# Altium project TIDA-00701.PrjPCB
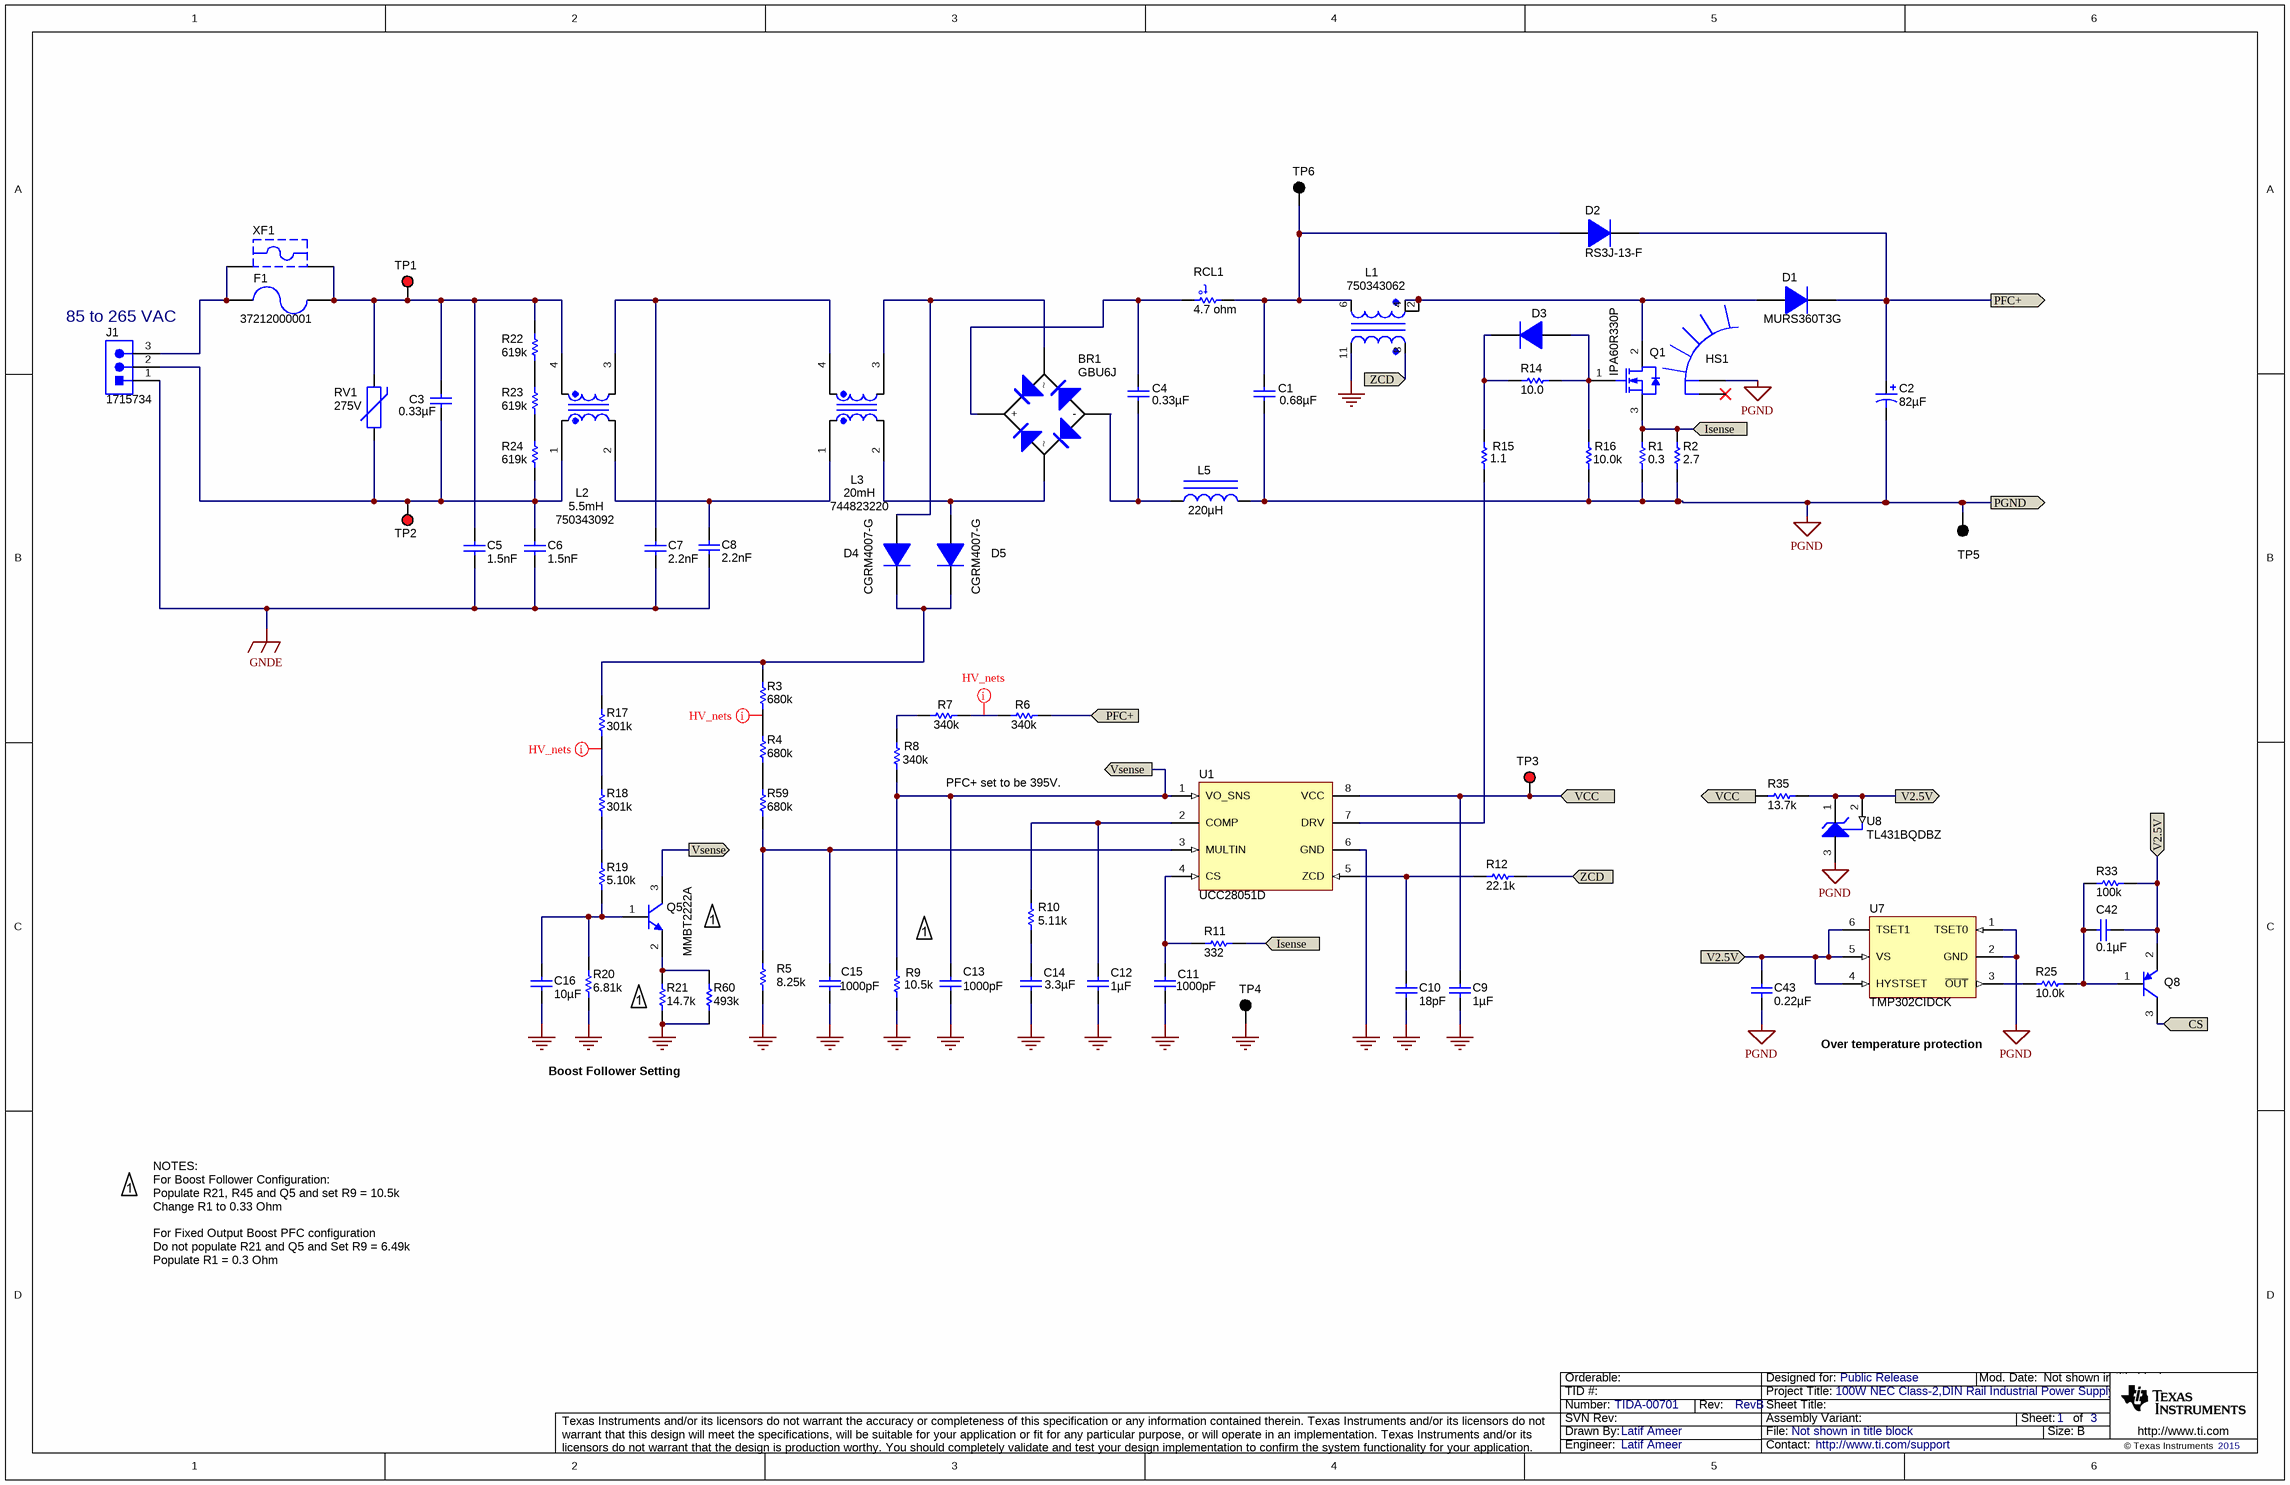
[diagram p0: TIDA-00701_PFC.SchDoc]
CopyrightYear: 2015; PCB_Layout: Manjunatha T N; PCB_Rev: RevB; PRJ_Customer: Public Release; PRJ_Engineer: Latif Ameer; PRJ_Number: TIDA-00701; PRJ_Title: 100W NEC Class-2,DIN Rail Industrial Power Supply; SCH_Rev: RevB; TechSupport: http://www.ti.com/support
3 sheets, 178 parts. Net scope: flat (ports and power ports of the same name join across sheets).
Board file: TIDA-00701_RevB.PcbDoc
Sheets:
  TIDA-00701_PFC.SchDoc
  TIDA-00701_Flyback.SchDoc
  Hardware_ANSI-B.SchDoc

## Sheet TIDA-00701_PFC.SchDoc
size 431 x 279 mm; Date: Not shown in title block; ApprovedBy: Not shown in title block; CheckedBy: Not shown in title block; Author: Not shown in title block; CompanyName: Not shown in title block; DrawnBy: Latif Ameer; Engineer: Not shown in title block; Organization: Not shown in title block; Address1: Not shown in title block; Address2: Not shown in title block; Address3: Not shown in title block; Address4: Not shown in title block; DocumentNumber: 1; Revision: Use project parameter SCH_Rev; SheetNumber: 1; SheetTotal: 3; PageSetup: Record=PageOptions¦CenterHorizontal=True¦CenterVertical=True¦PrintScale=1.00¦XCorrection=1.00¦YCorrection=1.00¦PrintKind=0¦BorderSize=5000000¦LeftOffset=0¦BottomOffset=0¦Orientation=2¦PaperLength=1000¦PaperWidth=1000¦Scale=100¦PaperSource=15¦PrintQuality=600¦MediaType=1¦DitherType=10¦PaperKind=Letter¦PrintScaleMode=1

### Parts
BR1  GBU6J  [GBU]
C1  ValueDisplayed: 0.68µF  [B32922_18.5mm]  (hidden comment: B32922C3684M)
C2  ValueDisplayed: 82µF  [CAPPRD750W80D1800H3150]  (hidden comment: UCY2W820MHD6)
C3  ValueDisplayed: 0.33µF  [B32922_14.5mm]  (hidden comment: B32922C3334M)
C4  ValueDisplayed: 0.33µF  [B32922_14.5mm]  (hidden comment: B32922C3334M)
C5  ValueDisplayed: 1.5nF  [E_900x700x900]  (hidden comment: CS75ZU2GA152MYNKA)
C6  ValueDisplayed: 1.5nF  [E_900x700x900]  (hidden comment: CS75ZU2GA152MYNKA)
C7  ValueDisplayed: 2.2nF  [E_900x700x900]  (hidden comment: CS80ZU2GA222MYNKA)
C8  ValueDisplayed: 2.2nF  [E_900x700x900]  (hidden comment: CS80ZU2GA222MYNKA)
C9  ValueDisplayed: 1µF  [0603]  (hidden comment: GRM188R61H105KAALD)
C10  ValueDisplayed: 18pF  [0603]  (hidden comment: GRM1885C1H180JA01D)
C11  ValueDisplayed: 1000pF  [0603]  (hidden comment: C1608C0G1H102J)
C12  ValueDisplayed: 1µF  [0603]  (hidden comment: C1608X5R1C105K)
C13  ValueDisplayed: 1000pF  [0603]  (hidden comment: C1608C0G1H102J)
C14  ValueDisplayed: 3.3µF  [0603]  (hidden comment: C1608X5R1E335K080AC)
C15  ValueDisplayed: 1000pF  [0603]  (hidden comment: C1608C0G1H102J)
C16  ValueDisplayed: 10µF  [0805_HV]  (hidden comment: C2012X5R1E106K125AB)
C42  ValueDisplayed: 0.1µF  [0603]  (hidden comment: GRM188R61C104KA01D)
C43  ValueDisplayed: 0.22µF  [0603]  (hidden comment: C1608X7R1C224K)
D1  MURS360T3G  [SMC]
D2  RS3J-13-F  [SMC]
D3  MMDL914-TP  [sod-323]  (value not drawn)
D4  CGRM4007-G  [MINI-SMA]
D5  CGRM4007-G  [MINI-SMA]
F1  37212000001  [FUSE_372]
HS1  593002B03400G  [HEATSINK_593002B03400G]  (value not drawn)
J1  1715734  [Phoenix_1715734]
L1  750343062  [XFMR_CTX16-17298]
L2  750343092  ValueDisplayed: 5.5mH  [750311982]
L3  744823220  ValueDisplayed: 20mH  [IND_WE-CMB_M]
L5  ValueDisplayed: 220µH  [IND_2118-V-RC]  (hidden comment: 2116-V-RC)
Q1  IPA60R330P  [TO-220AB]
Q5  MMBT2222A  [SOT-23]
Q8  MMBT4403WT1G  [SOT-323]  (value not drawn)
R1  ValueDisplayed: 0.3  [2010]  (hidden comment: CSRN2010FKR300)
R2  ValueDisplayed: 2.7  [2010]  (hidden comment: CRCW20102R70JNEF)
R3  ValueDisplayed: 680k  [1206]  (hidden comment: RC1206FR-07680KL)
R4  ValueDisplayed: 680k  [1206]  (hidden comment: RC1206FR-07680KL)
R5  ValueDisplayed: 8.25k  [0805_HV]  (hidden comment: CRCW08058K25FKEA)
R6  ValueDisplayed: 340k  [1206]  (hidden comment: CRCW1206340KFKEA)
R7  ValueDisplayed: 340k  [1206]  (hidden comment: CRCW1206340KFKEA)
R8  ValueDisplayed: 340k  [1206]  (hidden comment: CRCW1206340KFKEA)
R9  ValueDisplayed: 10.5k  [0603]  (hidden comment: CRCW060310K5FKEA)
R10  ValueDisplayed: 5.11k  [0603]  (hidden comment: CRCW06035K11FKEA)
R11  ValueDisplayed: 332  [0603]  (hidden comment: CRCW0603332RFKEA)
R12  ValueDisplayed: 22.1k  [0603]  (hidden comment: CRCW060322K1FKEA)
R14  ValueDisplayed: 10.0  [0805_HV]  (hidden comment: CRCW080510R0FKEA)
R15  ValueDisplayed: 1.1  [0805_HV]  (hidden comment: CRCW08051R10JNEA)
R16  ValueDisplayed: 10.0k  [0603]  (hidden comment: CRCW060310K0FKEA)
R17  ValueDisplayed: 301k  [1206]  (hidden comment: CRCW1206301KFKEA)
R18  ValueDisplayed: 301k  [1206]  (hidden comment: CRCW1206301KFKEA)
R19  ValueDisplayed: 5.10k  [1206]  (hidden comment: RC1206FR-075K1L)
R20  ValueDisplayed: 6.81k  [0805_HV]  (hidden comment: CRCW08056K81FKEA)
R21  ValueDisplayed: 14.7k  [0603]  (hidden comment: RC0603FR-0714K7L)
R22  ValueDisplayed: 619k  [1206]  (hidden comment: CRCW1206619KFKEA)
R23  ValueDisplayed: 619k  [1206]  (hidden comment: CRCW1206619KFKEA)
R24  ValueDisplayed: 619k  [1206]  (hidden comment: CRCW1206619KFKEA)
R25  ValueDisplayed: 10.0k  [0603]  (hidden comment: CRCW060310K0FKEA)
R33  ValueDisplayed: 100k  [0603]  (hidden comment: CRCW0603100KFKEA)
R35  ValueDisplayed: 13.7k  [0603]  (hidden comment: CRCW060313K7FKEA)
R59  ValueDisplayed: 680k  [1206]  (hidden comment: RC1206FR-07680KL)
R60  ValueDisplayed: 493k  [0603]  (hidden comment: RT0603BRD07493KL)
RCL1  value 4.7 ohm  [THERM_B57236S0]  (hidden comment: B57236S479M)
RV1  value 275V  [VAR_S10K275E2]  (hidden comment: S10K275E2)
TP1  5000  [Keystone5000]  (value not drawn)
TP2  5000  [Keystone5000]  (value not drawn)
TP3  5000  [Keystone5000]  (value not drawn)
TP4  5001  [Keystone5001]  (value not drawn)
TP5  5001  [Keystone5001]  (value not drawn)
TP6  5001  [Keystone5001]  (value not drawn)
U1  UCC28051D  [D0008A_N]
U7  TMP302CIDCK  [DCK0006A_N]
U8  TL431BQDBZ  [DBZ0003A_L]
XF1  56000001009  [FuseHolder_560000010]  (value not drawn)

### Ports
CS (in), Isense (in), PFC+ (in), PFC+ (out), PGND (out), V2.5V (in), V2.5V (out), VCC (in), Vsense (out), ZCD, ZCD (in)

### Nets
GND: C1.2 C2.2(-) C9.2 C10.2 C11.2 C12.2 C13.2 C14.2 C15.2 C16.2 C43.2 HS1.1 L1.11 L5.2 R1.1 R2.1 R5.1 R9.1 R16.2 R20.2 R21.2 R60.1 TP4.1 TP5.1 U1.6(GND) U7.1(TSET0) U7.2(GND) U8.3(ANODE) ; port PGND  [also labelled PGND]
GNDE: C5.2 C6.2 C7.2 C8.2 J1.1
VCC: C9.1 R35.1 TP3.1 U1.8(VCC) ; port VCC
NetBR1_1: BR1.1(+) C4.1 RCL1.2
NetBR1_2: BR1.2 D4.2(A) L3.3
NetBR1_3: BR1.3 D5.2(A) L3.2
NetBR1_4: BR1.4(-) C4.2 L5.1
NetC1_1: C1.1 D2.2(A) L1.6 RCL1.1 TP6.1
NetC2_1: C2.1(+) D1.1(K) D2.1(K) R6.1 ; port PFC+
NetC3_1: C3.1 C5.1 F1.1 L2.4 R22.1 RV1.2 TP1.1 XF1.1
NetC3_2: C3.2 C6.1 J1.2 L2.1 R24.2 RV1.1 TP2.1
NetC7_1: C7.1 L2.3 L3.4
NetC8_1: C8.1 L2.2 L3.1
NetC10_1: C10.1 R12.1 U1.5(ZCD)
NetC11_1: C11.1 R11.1 U1.4(CS)
NetC12_1: C12.1 R10.2 U1.2(COMP)
NetC13_1: C13.1 Q5.3(C) R8.1 R9.2 U1.1(VO_SNS) ; port Vsense
NetC14_1: C14.1 R10.1
NetC15_1: C15.1 R5.2 R59.2 U1.3(MULTIN)
NetC16_1: C16.1 Q5.1(B) R19.1 R20.1
NetC36_1: Q8.3(C) ; port CS
NetC42_1: C42.1 Q8.1(B) R25.2 R33.1
NetC42_2: C42.2 C43.1 Q8.2(E) R33.2 R35.2 U7.4(HYSTSET) U7.5(VS) U7.6(TSET1) U8.1(CATHODE) U8.2(REF) ; port V2.5V
NetD1_2: D1.2(A) L1.2 L1.4 Q1.2(D)
NetD3_1: D3.1(K) R14.1 R15.2
NetD3_2: D3.2(A) Q1.1(G) R14.2 R16.1
NetD4_1: D4.1(K) D5.1(K) R3.1 R17.2
NetF1_2: F1.2 J1.3 XF1.2
NetL1_8: L1.8 R12.2 ; port ZCD
NetQ1_3: Q1.3(S) R1.2 R2.2 R11.2 ; port Isense
NetQ5_2: Q5.2(E) R21.1 R60.2
NetR3_2: R3.2 R4.1
NetR4_2: R4.2 R59.1
NetR6_2: R6.2 R7.2
NetR7_1: R7.1 R8.2
NetR15_1: R15.1 U1.7(DRV)
NetR17_1: R17.1 R18.1
NetR18_2: R18.2 R19.2
NetR22_2: R22.2 R23.1
NetR23_2: R23.2 R24.1
NetR25_1: R25.1 U7.3(~{OUT})

Not connected (* = marked no-connect by the designer): HS1 2*

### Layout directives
net class HV_net: (no net found under the mark), NetR6_2, NetR17_1

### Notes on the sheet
- (near J1) 85 to 265 VAC
- PFC+ set to be 395V.
- Boost Follower Setting
- Over temperature protection
- NOTES:
  For Boost Follower Configuration:
  Populate R21, R45 and Q5 and set R9 = 10.5k
  Change R1 to 0.33 Ohm
  For Fixed Output Boost PFC configuration
  Do not populate R21 and Q5 and Set R9 = 6.49k
  Populate R1 = 0.3 Ohm

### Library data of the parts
BR1 = GBU4A-BP: RECT BRIDGE GPP 6A 600V GBU; Manufacturer: Micro Commercial Components; CompType: Diode; U/M: EA; Vf_V: 0.95; Io_A: 4; Vr_V: 50; Value2: 50V; TJmax_C: 150; RJC_CperW: 2.2
C1 = B32922C3684M: CAP, Film, 0.68 µF, 630 V, +/- 20%, TH; Manufacturer: TDK; Polarized: N; CompType: Capacitor; Value: 0.68uF; U/M: EA; Cap_F: 0.00000068; Tolerance_%: 20; Value1: Unknown; VDC_V: 630; Value2: 630V; TaMax_C: 110
C2 = EEUED2E820S: CAP ALUM 82UF 20% 450V RADIAL; Manufacturer: Nichicon; Polarized: Y; CompType: Capacitor; U/M: EA; Cap_F: 0.000082; Tolerance_%: 20; VDC_V: 450; IRMS_A: 730mA; TaMin_C: -25; TaMax_C: 105; AC_Derating: 0.3
C3 C4 = B32922C3334M: CAP, Film, 0.33 µF, 630 V, +/- 20%, TH; Manufacturer: TDK; Polarized: N; CompType: Capacitor; Value: 0.33uF; U/M: EA; Cap_F: 0.00000033; Tolerance_%: 20; Value1: Unknown; VDC_V: 630; Value2: 630V; TaMax_C: 110; AEC Category: Q200
C5 C6 = DE6E3KJ222MN3A: CAP CER 1500PF 300VAC 20% RADIAL; Manufacturer: TDK Corporation; Polarized: N; CompType: Capacitor; Value: 1.5nF; U/M: EA; Cap_F: 0.0000000022; Tolerance_%: 20; Value1: Unknown; VDC_V: 300; Value2: 300V; TempCo: E; TaMin_C: -40; TaMax_C: 125
C7 C8 = DE6E3KJ222MN3A: CAP CER 2200PF 300VAC 20% RADIAL; Manufacturer: TDK Corporation; Polarized: N; CompType: Capacitor; Value: 2.2nF; U/M: EA; Cap_F: 0.0000000022; Tolerance_%: 20; Value1: Unknown; VDC_V: 300; Value2: 300V; TempCo: E; TaMin_C: -40; TaMax_C: 125
C9 = GRM188R61H105KAALD: CAP, CERM, 1 µF, 50 V, +/- 10%, X5R, 0603; Manufacturer: MuRata; Polarized: N; CompType: Capacitor; Value: 1uF; U/M: EA; Cap_F: 0.000001; Tolerance_%: 10; Value1: Unknown; VDC_V: 50; Value2: 50V; TaMin_C: -55; TaMax_C: 85
C10 = GRM1885C1H180JA01D: CAP, CERM, 18 pF, 50 V, +/- 5%, C0G/NP0, 0603; Manufacturer: MuRata; Polarized: N; CompType: Capacitor; Value: 18pF; U/M: EA; Cap_F: 0.000000000018; Tolerance_%: 5; Value1: Unknown; VDC_V: 50; Value2: 50V; TaMin_C: -55; TaMax_C: 125
C11 C13 C15 = C1608C0G1H102J: CAP, CERM, 1000 pF, 50 V, +/- 5%, C0G/NP0, 0603; Manufacturer: TDK; Polarized: N; CompType: Capacitor; Value: 1000pF; U/M: EA; Cap_F: 0.000000001; Tolerance_%: 5; ESR_ohm: 0.0563; Value1: 0.0563 ohm; VDC_V: 50; Value2: 50V; TaMin_C: -55; TaMax_C: 125
C12 = C1608X5R1C105K: CAP, CERM, 1 µF, 16 V, +/- 10%, X5R, 0603; Manufacturer: TDK; Polarized: N; CompType: Capacitor; Value: 1uF; U/M: EA; Cap_F: 0.000001; Tolerance_%: 10; ESR_ohm: 0.0057; Value1: 0.0057 ohm; VDC_V: 16; Value2: 16V; TaMin_C: -55; TaMax_C: 85; AEC Category: Q200
C14 = C1608X5R1E335K080AC: CAP, CERM, 3.3 µF, 25 V, +/- 10%, X5R, 0603; Manufacturer: TDK; Polarized: N; CompType: Capacitor; Value: 3.3uF; U/M: EA; Cap_F: 0.0000033; Tolerance_%: 10; Value1: Unknown; VDC_V: 25; Value2: 25V; TaMin_C: -55; TaMax_C: 85
C16 = C2012X5R1E106K125AB: CAP, CERM, 10 µF, 25 V, +/- 10%, X5R, 0805; Manufacturer: TDK; Polarized: N; CompType: Capacitor; Value: 10uF; U/M: EA; Cap_F: 0.00001; Tolerance_%: 10; Value1: Unknown; VDC_V: 25; Value2: 25V; TaMin_C: -55; TaMax_C: 85; Cap_Case: 0805
C42 = GRM188R61C104KA01D: CAP, CERM, 0.1 µF, 16 V, +/- 10%, X5R, 0603; Manufacturer: MuRata; Polarized: N; CompType: Capacitor; Value: 0.1uF; U/M: EA; Cap_F: 0.0000001; Tolerance_%: 10; Value1: Unknown; VDC_V: 16; Value2: 16V; TaMin_C: -55; TaMax_C: 85
C43 = C1608X7R1C224K: CAP, CERM, 0.22 µF, 16 V, +/- 10%, X7R, 0603; Manufacturer: TDK; Polarized: N; CompType: Capacitor; Value: 0.22uF; U/M: EA; Cap_F: 0.00000022; Tolerance_%: 10; ESR_ohm: 0.0125; Value1: 0.0125 ohm; VDC_V: 16; Value2: 16V; TaMin_C: -55; TaMax_C: 125
D1 = MURS360T3G: Diode, Ultrafast, 600 V, 3 A, SMC; Manufacturer: ON Semiconductor; U/M: EA; Vf_V: 1.25; Value: 600V; Value1: 3A; Value2: 1.25V; Io_A: 3; Vr_V: 600; TJmax_C: 175; RJC_CperW: 11
D2 = RS3K-E3/9AT: DIODE GEN PURP 600V 3A SMC; Manufacturer: Diodes Incorporated; U/M: EA; Vf_V: 1.3; Value2: 1.3V; Io_A: 3; Vr_V: 600; TJmax_C: 150; RJC_CperW: 50; Type: Switching
D3 = MMDL914-TP: Diode, Switching, 100 V, 0.2 A, SOD-323; Manufacturer: Micro Commercial Components; Value: 100V; U/M: EA; Vf_V: 1; Value1: 0.2A; Value2: 1V; Io_A: 0.2; Vr_V: 100; TJmax_C: 150; RJC_CperW: 635
D4 D5 = CGRM4007-G: Diode, P-N, 1000 V, 1 A, 3.9x1.7x1.8mm; Manufacturer: Comchip Technology; U/M: EA; Vf_V: 1.1; Value: 1000V; Value1: 1A; Value2: 1.1V; Io_A: 1; Vr_V: 1000; TJmax_C: 150
F1 = 37212000001: Fuse, 2 A, 250 V, TH; Manufacturer: Littelfuse; U/M: EA; OpeningTime_200%_max: 2; VDC_V: 250; Vdrop: 0.085; Soldering_Wave_MaxTemp_C: 260; Soldering_Wave_MaxTime_s: 5
HS1 = 593002B00000G: HEATSINK TWISTED FIN TO-220 Vertical; Manufacturer: Aavid Thermalloy; SymbolCreator: a0799628; Value: 13.4°C/W
J1 = 1715734: TERM BLOCK 3POS 5.08MM, TH; Manufacturer: Phoenix Contact; SymbolCreator: a0799628; CompType: Header; U/M: EA
L1 = XFMR_CTX16-17298: PFC choke with primary side sensing winding; Manufacturer: Wurth; Value: 330uH
L2 = 744823210: Coupled inductor, 5.5mH+/-32%, 2.5 A, 0.040 ohm; Manufacturer: Wurth Elektronik; Value: 5.5mH=/-32%; Ind_H: 5.5e-3; Tolerance_%: 32
L3 = 744823210: Coupled inductor, 20 mH, 1.5A, 0.270 ohm, +/- 30%, TH; Manufacturer: Wurth Elektronik; SymbolCreator: a0412235; Value: 20mH; Ind_H: 20.0E-3; DCR_ohm: 0.270; Tolerance_%: 30
L5 = PM2110-1R0M-RC: Inductor, Toroid, 220µH, 2.4 A, 0.120 ohm, TH; Manufacturer: Bourns; Value: 220uH; Ind_H: 220E-6; Imax_A: 2.4; Irms: 2.4A @ 30C rise; DCR_ohm: 0.120; Value2: 2.4A; AEC Category: Q200
Q1 = IPP60R190P6: MOSFET N-CH 600V 10.6A TO220; PartNumber: IPA60R330P6XKSA1; Manufacturer: Infineon Technologies; SymbolCreator: x0199378
Q5 = MMBT2222A, Fairchild Semiconductor: Transistor, NPN, 40 V, 0.15 A, SOT-23; CompType: BJT; PNP: 0; NPN: 1; Vceo_V: 40; Vcesat1_V: 0.3; Value: 40 V; IcRated_A: 0.15; Value1: 0.15 A; HfeMax: 300; TaMin_C: -55; TaMax_C: 150; U/M: EA; AEC Category: Q101
Q8 = MMBT2907A, Fairchild Semiconductor: Transistor, PNP, 40 V, 0.6 A, SOT-323; CompType: BJT; PNP: 1; NPN: 0; Vceo_V: 40; Vcesat1_V: 0.75; Value: 40 V; IcRated_A: 0.8; Value1: 0.6 A; HfeMax: 300; TaMin_C: -55; TaMax_C: 150; U/M: EA
R1 = CSRN2010FKR300: RES, 0.3, 1%, 1 W, 2010; Manufacturer: Stackpole Electronics Inc; CompType: Resistor; Value: 0.3; Value_Code: R300; Tolerance_%: 1; Value2: 1W; TempCo: 250 ppm/C; EIA_Code: E96; U/M: EA; AEC Category: Q200
R2 = CRCW20102R70JNEF: RES, 2.7, 5%, 0.75 W, 2010; Manufacturer: Vishay-Dale; CompType: Resistor; Value: 2.7; Value_Code: 2R70; Tolerance_%: 5; Power_W: 0.75; Value2: 0.75W; VDC_V: 400; TempCo: 200 ppm/C; EIA_Code: E24; U/M: EA
R3 R4 R59 = RC1206FR-07680KL: RES, 680 k, 1%, 0.25 W, 1206; Manufacturer: Yageo America; Value: 680k; CompType: Resistor; Res_ohm: 680000; Tolerance_%: 1; Power_W: 0.25; Value2: 0.25W; VDC_V: 200; TempCo: 100 ppm/C; U/M: EA
R5 = CRCW08058K25FKEA: RES, 8.25 k, 1%, 0.125 W, 0805; Manufacturer: Vishay-Dale; CompType: Resistor; Value: 8.25k; Res_ohm: 8250; Value_Code: 8k25; Tolerance_%: 1; Power_W: 0.125; Value2: 0.125W; VDC_V: 150; TempCo: 100 ppm/C; EIA_Code: E96; U/M: EA; AEC Category: Q200
R6-R8 = CRCW1206340KFKEA: RES, 340 k, 1%, 0.25 W, 1206; Manufacturer: Vishay-Dale; Value: 340k; CompType: Resistor; Res_ohm: 340000; Tolerance_%: 1; Power_W: 0.25; Value2: 0.25W; VDC_V: 200; TempCo: 100 ppm/C; EIA_Code: E96; U/M: EA
R9 = CRCW060310K5FKEA: RES, 10.5 k, 1%, 0.1 W, 0603; Manufacturer: Vishay-Dale; CompType: Resistor; Value: 10.5k; Res_ohm: 10500; Value_Code: 10k5; Tolerance_%: 1; Power_W: 0.1; Value2: 0.1W; VDC_V: 75; TempCo: 100 ppm/C; EIA_Code: E96; U/M: EA; AEC Category: Q200
R10 = CRCW06035K11FKEA: RES, 5.11 k, 1%, 0.1 W, 0603; Manufacturer: Vishay-Dale; CompType: Resistor; Value: 5.11k; Res_ohm: 5110; Value_Code: 5k11; Tolerance_%: 1; Power_W: 0.1; Value2: 0.1W; VDC_V: 75; TempCo: 100 ppm/C; EIA_Code: E96; U/M: EA
R11 = CRCW0603332RFKEA: RES, 332, 1%, 0.1 W, 0603; Manufacturer: Vishay-Dale; CompType: Resistor; Value: 332; Value_Code: 332R; Tolerance_%: 1; Power_W: 0.1; Value2: 0.1W; VDC_V: 75; TempCo: 100 ppm/C; EIA_Code: E96; U/M: EA
R12 = CRCW060322K1FKEA: RES, 22.1 k, 1%, 0.1 W, 0603; Manufacturer: Vishay-Dale; CompType: Resistor; Value: 22.1k; Res_ohm: 22100; Value_Code: 22k1; Tolerance_%: 1; Power_W: 0.1; Value2: 0.1W; VDC_V: 75; TempCo: 100 ppm/C; EIA_Code: E96; U/M: EA
R14 = CRCW080510R0FKEA: RES, 10.0, 1%, 0.125 W, 0805; Manufacturer: Vishay-Dale; CompType: Resistor; Value: 10.0; Res_ohm: 10; Value_Code: 10R0; Tolerance_%: 1; Power_W: 0.125; Value2: 0.125W; VDC_V: 150; TempCo: 100 ppm/C; EIA_Code: E96; U/M: EA
R15 = CRCW08051R10JNEA: RES, 1.1, 5%, 0.125 W, 0805; Manufacturer: Vishay-Dale; CompType: Resistor; Value: 1.1; Value_Code: 1R10; Tolerance_%: 5; Power_W: 0.125; Value2: 0.125W; VDC_V: 150; TempCo: 200 ppm/C; EIA_Code: E24; U/M: EA; AEC Category: Q200
R16 R25 = CRCW060310K0FKEA: RES, 10.0 k, 1%, 0.1 W, 0603; Manufacturer: Vishay-Dale; CompType: Resistor; Value: 10.0k; Res_ohm: 10000; Value_Code: 10k0; Tolerance_%: 1; Power_W: 0.1; Value2: 0.1W; VDC_V: 75; TempCo: 100 ppm/C; EIA_Code: E96; U/M: EA
R17 R18 = CRCW1206301KFKEA: RES, 301 k, 1%, 0.25 W, 1206; Manufacturer: Vishay-Dale; CompType: Resistor; Value: 301k; Res_ohm: 301000; Tolerance_%: 1; Power_W: 0.25; Value2: 0.25W; VDC_V: 200; TempCo: 100 ppm/C; EIA_Code: E96; U/M: EA; AEC Category: Q200
R19 = RC1206FR-075K1L: RES, 5.10 k, 1%, 0.25 W, 1206; Manufacturer: Yageo America; CompType: Resistor; Value: 5.10k; Res_ohm: 5100; Value_Code: 5k10; Tolerance_%: 1; Power_W: 0.25; Value2: 0.25W; VDC_V: 200; TempCo: 100 ppm/C; U/M: EA; AEC Category: Q200
R20 = CRCW08056K81FKEA: RES, 6.81 k, 1%, 0.125 W, 0805; Manufacturer: Vishay-Dale; CompType: Resistor; Value: 6.81k; Res_ohm: 6810; Value_Code: 6k81; Tolerance_%: 1; Power_W: 0.125; Value2: 0.125W; VDC_V: 150; TempCo: 100 ppm/C; EIA_Code: E96; U/M: EA; AEC Category: Q200
R21 = RC0603FR-0714K7L: RES, 14.7 k, 1%, 0.1 W, 0603; Manufacturer: Yageo America; CompType: Resistor; Value: 14.7k; Res_ohm: 14700; Value_Code: 14k7; Tolerance_%: 1; Power_W: 0.1; Value2: 0.1W; VDC_V: 150; TempCo: 200 ppm/C; EIA_Code: E96; U/M: EA; AEC Category: Q200
R22-R24 = CRCW1206619KFKEA: RES, 619 k, 1%, 0.25 W, 1206; Manufacturer: Vishay-Dale; Value: 619k; CompType: Resistor; Res_ohm: 619000; Tolerance_%: 1; Power_W: 0.25; Value2: 0.25W; VDC_V: 200; TempCo: 100 ppm/C; EIA_Code: E96; U/M: EA; AEC Category: Q200
R33 = CRCW0603100KFKEA: RES, 100 k, 1%, 0.1 W, 0603; Manufacturer: Vishay-Dale; CompType: Resistor; Value: 100k; Res_ohm: 100000; Tolerance_%: 1; Power_W: 0.1; Value2: 0.1W; VDC_V: 75; TempCo: 100 ppm/C; EIA_Code: E96; U/M: EA
R35 = CRCW060313K7FKEA: RES, 13.7 k, 1%, 0.1 W, 0603; Manufacturer: Vishay-Dale; CompType: Resistor; Value: 13.7k; Res_ohm: 13700; Value_Code: 13k7; Tolerance_%: 1; Power_W: 0.1; Value2: 0.1W; VDC_V: 75; TempCo: 100 ppm/C; EIA_Code: E96; U/M: EA
R60 = RT0603BRD07493KL: RES, 493 k, 0.1%, 0.1 W, 0603; Manufacturer: Yageo America; CompType: Resistor; Value: 493k; Res_ohm: 493000; Tolerance_%: 0.1; Value2: 0.1W; VDC_V: 75; TempCo: 25 ppm/C; EIA_Code: E192; U/M: EA; AEC Category: Q200
RCL1 = B57236S0100M000: ICL 4.7 OHM 20% 4.6A 11.51MM; Manufacturer: TDK; CompType: ThermistorNTC; Tolerance_%: 20; Power_W: 2.1; U/M: EA; TaMin_C: -55; TaMax_C: 170
RV1 = S10K275E2: Varistor 275V RMS 10MM Radial, TH; Manufacturer: EPCOS Inc; SymbolCreator: a0412235
TP1-TP3 = 5000: Test Point, Miniature, Red, TH; Manufacturer: Keystone; CompType: Test Point Loop; U/M: EA
TP4-TP6 = 5001: Test Point, Miniature, Black, TH; Manufacturer: Keystone; CompType: Test Point Loop; U/M: EA
U1 = UCC28051D: TRANSITION MODE PFC CONTROLLER, D0008A; Alternate Manufacturer: None; Manufacturer: Texas Instruments; SymbolCreator: a0412238; CompType: IC; U/M: EA
U7 = TMP300BIDCK: 1.8V, Resistor-Programmable TEMPERATURE SWITCH and ANALOG OUT TEMPERATURE SENSOR, DCK0006A; Alternate Manufacturer: None; Manufacturer: Texas Instruments; SymbolCreator: a0412235; CompType: IC; U/M: EA
U8 = TL431BQDBZ: PRECISION PROGRAMMABLE REFERENCE, DBZ0003A; Alternate Manufacturer: Texas Instruments; SymbolCreator: a0412235; CompType: IC; U/M: EA
XF1 = 56000001009: FUSE HOLDER RADIAL 250V 6.3A PCB; Manufacturer: Littelfuse; SymbolCreator: a0412235; Value: TR5

## Sheet TIDA-00701_Flyback.SchDoc
size 431 x 279 mm; Date: Not shown in title block; ApprovedBy: Not shown in title block; CheckedBy: Not shown in title block; Author: Not shown in title block; CompanyName: Not shown in title block; DrawnBy: Latif Ameer; Engineer: Not shown in title block; Organization: Not shown in title block; Address1: Not shown in title block; Address2: Not shown in title block; Address3: Not shown in title block; Address4: Not shown in title block; DocumentNumber: 1; Revision: Use project parameter SCH_Rev; SheetNumber: 2; SheetTotal: 3; PageSetup: Record=PageOptions¦CenterHorizontal=True¦CenterVertical=True¦PrintScale=1.00¦XCorrection=1.00¦YCorrection=1.00¦PrintKind=0¦BorderSize=5000000¦LeftOffset=0¦BottomOffset=0¦Orientation=2¦PaperLength=1000¦PaperWidth=1000¦Scale=100¦PaperSource=15¦PrintQuality=600¦MediaType=1¦DitherType=10¦PaperKind=Letter¦PrintScaleMode=1
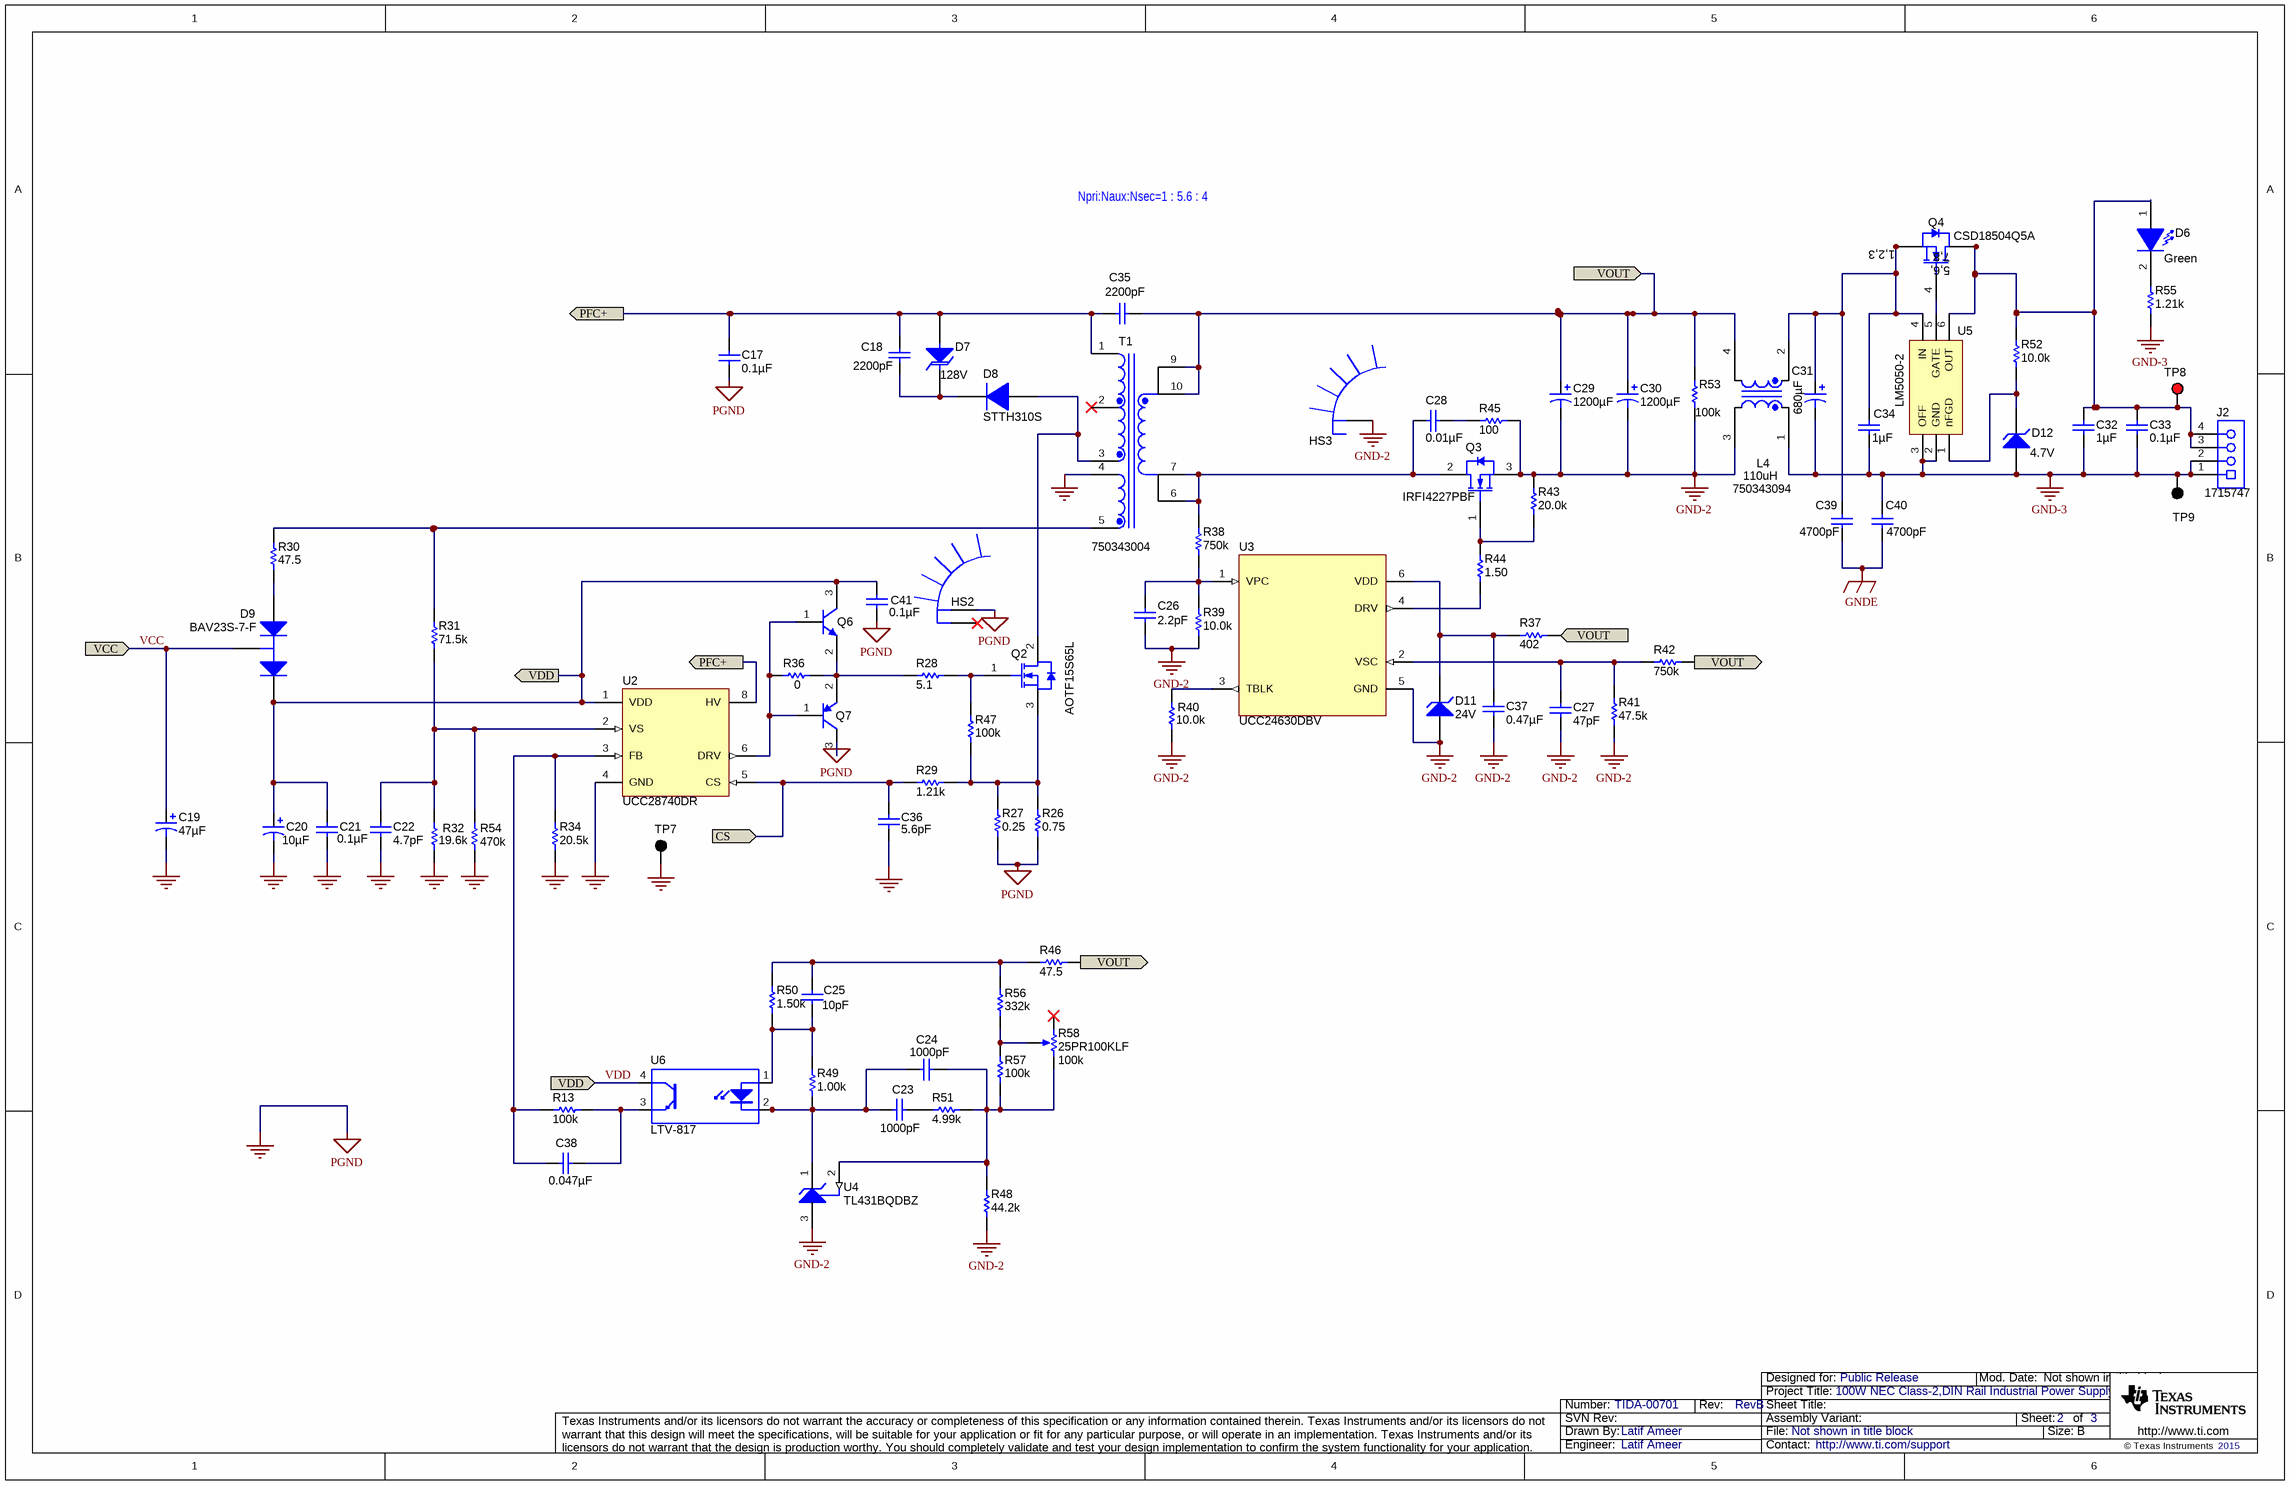
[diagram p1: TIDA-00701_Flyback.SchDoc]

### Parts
C17  ValueDisplayed: 0.1µF  [B32921_1300x1200x600]  (hidden comment: B32921C3104M)
C18  ValueDisplayed: 2200pF  [1206]  (hidden comment: C3216X7R2J222K)
C19  ValueDisplayed: 47µF  [ZLJ_500x1100]  (hidden comment: 35ZLJ47MTA5X11)
C20  ValueDisplayed: 10µF  [FC_400x1100]  (hidden comment: UVR1H100MDD6TP)
C21  ValueDisplayed: 0.1µF  [0603]  (hidden comment: C1608X7R1H104K)
C22  ValueDisplayed: 4.7pF  [0603]  (hidden comment: 06035A4R7CAT2A)
C23  ValueDisplayed: 1000pF  [0603]  (hidden comment: C1608C0G1H102J)
C24  ValueDisplayed: 1000pF  [0603]  (hidden comment: C1608C0G1H102J)
C25  ValueDisplayed: 10pF  [0603]  (hidden comment: 06035A100JAT2A)
C26  ValueDisplayed: 2.2pF  [0603]  (hidden comment: 06035A2R2CAT2A)
C27  ValueDisplayed: 47pF  [0603]  (hidden comment: 06035A470JAT2A)
C28  ValueDisplayed: 0.01µF  [0805_HV]  (hidden comment: C2012X7R2E103K)
C29  ValueDisplayed: 1200µF  [CAPPRD500W60D1250H3000]  (hidden comment: EKY-350ELL122MK30S)
C30  ValueDisplayed: 1200µF  [CAPPRD500W60D1250H3000]  (hidden comment: EKY-350ELL122MK30S)
C31  ValueDisplayed: 680µF  [CAPPRD500W60D1000H3000]  (hidden comment: 680uF)
C32  ValueDisplayed: 1µF  [1206]  (hidden comment: C3216X7R1H105K)
C33  ValueDisplayed: 0.1µF  [1206]  (hidden comment: C1206C104J5RACTU)
C34  ValueDisplayed: 1µF  [0603]  (hidden comment: GRM188R61H105KAALD)
C35  ValueDisplayed: 2200pF  [E_900x700x900]  (hidden comment: CS80ZU2GA222MYNKA)
C36  ValueDisplayed: 5.6pF  [0603]  (hidden comment: 06035A5R6CAT2A)
C37  ValueDisplayed: 0.47µF  [0805_HV]  (hidden comment: GRM21BR71H474KA88L)
C38  ValueDisplayed: 0.047µF  [0603]  (hidden comment: C1608X7R1H473K)
C39  ValueDisplayed: 4700pF  [CAPRD750W60D750H1050]  (hidden comment: VY2472M49Y5US63V7)
C40  ValueDisplayed: 4700pF  [CAPRD750W60D750H1050]  (hidden comment: VY2472M49Y5US63V7)
C41  ValueDisplayed: 0.1µF  [0603]  (hidden comment: C1608X7R1H104K)
D6  value Green  [LED_HLMP1523]  (hidden comment: HLMP1503)
D7  value 128V  [DO-201AD_Vert]  (hidden comment: 1.5KE150A)
D8  STTH310S  [SMC]
D9  BAV23S-7-F  [SOT-23]
D11  value 24V  [SOD-123]  (hidden comment: MMSZ5252B-7-F)
D12  value 4.7V  [SOD-523]  (hidden comment: BZT52C4V7T-7)
HS2  593002B03400G  [HEATSINK_593002B03400G]  (value not drawn)
HS3  V7237C  [HEATSINK_V7237C]  (value not drawn)
J2  1715747  [Phoenix_1715747]
L4  750343094  ValueDisplayed: 110uH  [IND_750343094]
Q2  AOTF15S65L  [TO-220_FullPAK_Offset]
Q3  IRFI4227PBF  [TO-220AB]
Q4  CSD18504Q5A  [TRANS_NexFET_Q5A]
Q6  MMBT4401WT1G  [SOT-323]  (value not drawn)
Q7  MMBT4403WT1G  [SOT-323]  (value not drawn)
R13  ValueDisplayed: 100k  [0603]  (hidden comment: CRCW0603100KFKEA)
R26  ValueDisplayed: 0.75  [2010]  (hidden comment: CSRN2010FKR750)
R27  ValueDisplayed: 0.25  [2010]  (hidden comment: CSRN2010FKR250)
R28  ValueDisplayed: 5.1  [0603]  (hidden comment: CRCW06035R10JNEA)
R29  ValueDisplayed: 1.21k  [0603]  (hidden comment: CRCW06031K21FKEA)
R30  ValueDisplayed: 47.5  [0805_HV]  (hidden comment: CRCW080547R5FKEA)
R31  ValueDisplayed: 71.5k  [0603]  (hidden comment: CRCW060371K5FKEA)
R32  ValueDisplayed: 19.6k  [0603]  (hidden comment: CRCW060319K6FKEA)
R34  ValueDisplayed: 20.5k  [0603]  (hidden comment: CRCW060320K5FKEA)
R36  ValueDisplayed: 0  [0603]  (hidden comment: CRCW06030000Z0EA)
R37  ValueDisplayed: 402  [0603]  (hidden comment: CRCW0603402RFKEA)
R38  ValueDisplayed: 750k  [0603]  (hidden comment: CRCW0603750KFKEA)
R39  ValueDisplayed: 10.0k  [0603]  (hidden comment: CRCW060310K0FKEA)
R40  ValueDisplayed: 10.0k  [0603]  (hidden comment: CRCW060310K0FKEA)
R41  ValueDisplayed: 47.5k  [0603]  (hidden comment: CRCW060347K5FKEA)
R42  ValueDisplayed: 750k  [0603]  (hidden comment: CRCW0603750KFKEA)
R43  ValueDisplayed: 20.0k  [0603]  (hidden comment: CRCW060320K0FKEA)
R44  ValueDisplayed: 1.50  [0603]  (hidden comment: CRCW06031R50FKEA)
R45  ValueDisplayed: 100  [1206]  (hidden comment: CRCW1206100RFKEA)
R46  ValueDisplayed: 47.5  [0603]  (hidden comment: CRCW060347R5FKEA)
R47  ValueDisplayed: 100k  [0603]  (hidden comment: CRCW0603100KFKEA)
R48  ValueDisplayed: 44.2k  [0603]  (hidden comment: CRCW060344K2FKEA)
R49  ValueDisplayed: 1.00k  [0603]  (hidden comment: CRCW06031K00FKEA)
R50  ValueDisplayed: 1.50k  [0603]  (hidden comment: CRCW06031K50FKEA)
R51  ValueDisplayed: 4.99k  [0603]  (hidden comment: CRCW06034K99FKEA)
R52  ValueDisplayed: 10.0k  [0603]  (hidden comment: CRCW060310K0FKEA)
R53  ValueDisplayed: 100k  [1206]  (hidden comment: CRCW1206100KFKEA)
R54  ValueDisplayed: 470k  [0603]  (hidden comment: RC0603FR-07470KL)
R55  ValueDisplayed: 1.21k  [0603]  (hidden comment: CRCW06031K21FKEA)
R56  ValueDisplayed: 332k  [0603]  (hidden comment: CRCW0603332KFKEA)
R57  ValueDisplayed: 100k  [0603]  (hidden comment: CRCW0603100KFKEA)
R58  25PR100KLF  value 100k  [POT_25PXXXXXX]
T1  750343004  [WE_75034300X]
TP7  5001  [Keystone5001]  (value not drawn)
TP8  5000  [Keystone5000]  (value not drawn)
TP9  5001  [Keystone5001]  (value not drawn)
U2  UCC28740DR  [D0007A_N]
U3  UCC24630DBV  [DBV0006A_N]
U4  TL431BQDBZ  [DBZ0003A_L]
U5  LM5050-2  [tsop-6]
U6  LTV-817  [DIP762W60P254L460H350Q4B]

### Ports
CS (in), PFC+, VCC (in), VDD (in), VDD (out), VOUT (in)

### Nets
GND: C17.2 C19.2(-) C20.2(-) C21.2 C22.2 C36.2 C41.2 HS2.1 Q7.3(C) R26.1 R27.1 R32.1 R34.1 R54.1 T1.4 TP7.1 U2.4(GND)  [also labelled PGND]
GND-2: C26.2 C27.1 C29.2(-) C30.2(-) C37.1 D11.2(A) HS3.1 L4.3 Q3.3(S) R39.1 R40.2 R41.2 R43.2 R45.2 R48.2 R53.1 U3.5(GND) U4.3(ANODE)
GND-3: C31.2(-) C32.2 C33.2 C34.2 C40.1 D12.2(A) J2.1 J2.2 L4.1 R55.1 TP9.1 U5.2(GND) U5.3(OFF)
GNDE: C39.2 C40.2
VCC: C19.1(+) D9.3(C) ; port VCC
VDD: C20.1(+) C21.1 C41.1 D9.2(K) Q6.3(C) U2.1(VDD) U6.4(C) ; port VDD
NetC2_1: C17.1 C18.1 C35.1 D7.2(A) T1.1 U2.8(HV) ; port PFC+
NetC18_2: C18.2 D7.1(K) D8.1(K)
NetC22_1: C22.1 R31.1 R32.2 R54.2 U2.2(VS)
NetC23_1: C23.1 C24.1 R49.1 U4.1(CATHODE) U6.2(K)
NetC23_2: C23.2 R51.2
NetC24_2: C24.2 R48.1 R51.1 R57.1 R58.3(CW) U4.2(REF)
NetC25_1: C25.1 R46.2 R50.1 R56.2
NetC25_2: C25.2 R49.2 R50.2 U6.1(A)
NetC26_1: C26.1 R38.1 R39.2 U3.1(VPC)
NetC27_2: C27.2 R41.1 R42.2 U3.2(VSC)
NetC28_1: C28.1 R45.1
NetC28_2: C28.2 Q3.2(D) R38.2 T1.6 T1.7
NetC29_1: C29.1(+) C30.1(+) C35.2 L4.4 R37.1 R42.1 R46.1 R53.2 T1.9 T1.10 ; port VOUT
NetC31_1: C31.1(+) C34.1 C39.1 L4.2 Q4.1(S) Q4.2(S) Q4.3(S) U5.4(IN)
NetC32_1: C32.1 C33.1 D6.1(A) J2.3 J2.4 Q4.5(D) Q4.6(D) Q4.7(D) Q4.8(D) Q4.9(D) R52.1 TP8.1 U5.6(OUT)
NetC36_1: C36.1 R29.1 U2.5(CS) ; port CS
NetC37_2: C37.2 D11.1(K) R37.2 U3.6(VDD)
NetC38_1: C38.1 R13.2 R34.2 U2.3(FB)
NetC38_2: C38.2 R13.1 U6.3(E)
NetD6_2: D6.2(K) R55.2
NetD8_2: D8.2(A) Q2.2(D) T1.3
NetD9_1: D9.1(A) R30.1
NetD12_1: D12.1(K) R52.2 U5.1(nFGD)
NetQ2_1: Q2.1(G) R28.2 R47.2
NetQ2_3: Q2.3(S) R26.2 R27.2 R29.2 R47.1
NetQ3_1: Q3.1(G) R43.1 R44.2
NetQ4_4: Q4.4(G) U5.5(GATE)
NetQ6_1: Q6.1(B) Q7.1(B) R36.1 U2.6(DRV)
NetQ6_2: Q6.2(E) Q7.2(E) R28.1 R36.2
NetR30_2: R30.2 R31.2 T1.5
NetR40_1: R40.1 U3.3(TBLK)
NetR44_1: R44.1 U3.4(DRV)
NetR56_1: R56.1 R57.2 R58.2(WIPER)

Not connected (* = marked no-connect by the designer): HS2 2*; R58 1(CCW)*; T1 2*

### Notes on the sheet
- Npri:Naux:Nsec=1 : 5.6 : 4

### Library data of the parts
C17 = B32921C3104M: CAP, Film, 0.1 µF, 305 V, +/- 20%, TH; Manufacturer: TDK; Polarized: N; CompType: Capacitor; Value: 0.1uF; U/M: EA; Cap_F: 0.0000001; Tolerance_%: 20; Value1: Unknown; VDC_V: 305; Value2: 305V; TaMin_C: -40; TaMax_C: 110; Cap_Case: 13x12x6mm
C18 = C3216X7R2J222K: CAP, CERM, 2200 pF, 630 V, +/- 10%, X7R, 1206; Manufacturer: TDK; Polarized: N; CompType: Capacitor; Value: 2200pF; U/M: EA; Cap_F: 0.0000000022; Tolerance_%: 10; ESR_ohm: 0.151; Value1: 0.151 ohm; VDC_V: 630; Value2: 630V; TaMin_C: -55; TaMax_C: 125; AEC Category: Q200
C19 = 35ZLJ47MTA5X11: CAP, AL, 47 µF, 35 V, +/- 20%, 0.4 ohm, TH; Manufacturer: Rubycon; Polarized: Y; CompType: Capacitor; Value: 47uF; U/M: EA; Cap_F: 0.000047; Tolerance_%: 20; ESR_ohm: 0.4; Value1: 0.4 ohm; VDC_V: 35; Value2: 35V; IRMS_A: 0.45; TaMin_C: -40; TaMax_C: 105; Cap_Case: 5x11mm
C20 = EEU-FC1H100: CAP ALUM 10UF 20% 50V RADIAL; Manufacturer: Nichicon; Polarized: Y; CompType: Capacitor; U/M: EA; Cap_F: 0.00001; Tolerance_%: 20; Value1: 2.5 ohm; VDC_V: 50; ESR_ohm: 2.5; IRMS_A: 0.09; TaMin_C: -55; TaMax_C: 105; Cap_Case: 4.0x11.0
C21 C41 = C1608X7R1H104K: CAP, CERM, 0.1 µF, 50 V, +/- 10%, X7R, 0603; Manufacturer: TDK; Polarized: N; CompType: Capacitor; Value: 0.1uF; U/M: EA; Cap_F: 0.0000001; Tolerance_%: 10; ESR_ohm: 0.017; Value1: 0.017 ohm; VDC_V: 50; Value2: 50V; TaMin_C: -55; TaMax_C: 125
C22 = 06035A4R7CAT2A: CAP, CERM, 4.7 pF, 50 V, +/- 5%, C0G/NP0, 0603; Manufacturer: AVX; Polarized: N; CompType: Capacitor; Value: 4.7pF; U/M: EA; Cap_F: 0.0000000000047; Tolerance_%: 5; ESR_ohm: 0.633; Value1: 0.633 ohm; VDC_V: 50; Value2: 50V; TaMin_C: -55; TaMax_C: 125
C23 C24 = C1608C0G1H102J: as C11 on sheet TIDA-00701_PFC
C25 = 06035A100JAT2A: CAP, CERM, 10 pF, 50 V, +/- 5%, C0G/NP0, 0603; Manufacturer: AVX; Polarized: N; CompType: Capacitor; Value: 10pF; U/M: EA; Cap_F: 0.00000000001; Tolerance_%: 5; ESR_ohm: 0.403; Value1: 0.403 ohm; VDC_V: 50; Value2: 50V; TaMin_C: -55; TaMax_C: 125
C26 = 06035A2R2CAT2A: CAP, CERM, 2.2 pF, 50 V, +/- 11%, C0G/NP0, 0603; Manufacturer: AVX; Polarized: N; CompType: Capacitor; Value: 2.2pF; U/M: EA; Cap_F: 0.0000000000022; Tolerance_%: 11; ESR_ohm: 1.033; Value1: 1.033 ohm; VDC_V: 50; Value2: 50V; TaMin_C: -55; TaMax_C: 125
C27 = 06035A470JAT2A: CAP, CERM, 47 pF, 50 V, +/- 5%, C0G/NP0, 0603; Manufacturer: AVX; Polarized: N; CompType: Capacitor; Value: 47pF; U/M: EA; Cap_F: 0.000000000047; Tolerance_%: 5; ESR_ohm: 0.174; Value1: 0.174 ohm; VDC_V: 50; Value2: 50V; TaMin_C: -55; TaMax_C: 125
C28 = C2012X7R2E103K: CAP, CERM, 0.01 µF, 250 V, +/- 10%, X7R, 0805; Manufacturer: TDK; Polarized: N; CompType: Capacitor; Value: 0.01uF; U/M: EA; Cap_F: 0.00000001; Tolerance_%: 10; ESR_ohm: 0.0681; Value1: 0.0681 ohm; VDC_V: 250; Value2: 250V; TaMin_C: -55; TaMax_C: 125; Cap_Case: 0805
C29 C30 = EKY-160ELL102MK15S: CAP, AL, 1200 µF, 35 V, +/- 20%, 0.024 ohm, TH; Manufacturer: United Chemi-Con; Polarized: Y; CompType: Capacitor; Value: 1200uF; U/M: EA; Tolerance_%: 20; Value1: 24mOhm; VDC_V: 35; Value2: 35V; ESR_ohm: 24 mOhm; IRMS_A: 2.65A; TaMin_C: -40; TaMax_C: 105; Cap_Case: 12.5x30.0
C31 = EKY-160ELL152MJ30S: CAP ALUM 680UF 20% 35V RADIAL; PartNumber: EKY-350ELL681MJ30S; Manufacturer: Chemi-Con; Polarized: Y; CompType: Capacitor; U/M: EA; Cap_F: 0.0015; Tolerance_%: 20; Value1: 0.031 ohm; VDC_V: 35; ESR_ohm: 0.031; IRMS_A: 1.91; TaMin_C: -40; TaMax_C: 105; Cap_Case: 10x30
C32 = C3216X7R1H105K: CAP, CERM, 1 µF, 50 V, +/- 10%, X7R, 1206; Manufacturer: TDK; Polarized: N; CompType: Capacitor; Value: 1uF; U/M: EA; Cap_F: 0.000001; Tolerance_%: 10; ESR_ohm: 0.01; Value1: 0.01 ohm; VDC_V: 50; Value2: 50V; IRMS_A: 3.2; TaMin_C: -55; TaMax_C: 125
C33 = C1206C104J5RACTU: CAP, CERM, 0.1 µF, 50 V, +/- 5%, X7R, 1206; Manufacturer: Kemet; Polarized: N; CompType: Capacitor; Value: 0.1uF; U/M: EA; Cap_F: 0.0000001; Tolerance_%: 5; ESR_ohm: 0.059; Value1: 0.059 ohm; VDC_V: 50; Value2: 50V; IRMS_A: 1.2; TaMin_C: -55; TaMax_C: 125
C34 = GRM188R61H105KAALD: as C9 on sheet TIDA-00701_PFC
C35 = DE6E3KJ222MN3A: as C7 on sheet TIDA-00701_PFC
C36 = 06035A5R6CAT2A: CAP, CERM, 5.6 pF, 50 V, +/- 5%, C0G/NP0, 0603; Manufacturer: AVX; Polarized: N; CompType: Capacitor; Value: 5.6pF; U/M: EA; Cap_F: 0.0000000000056; Tolerance_%: 5; ESR_ohm: 0.568; Value1: 0.568 ohm; VDC_V: 50; Value2: 50V; TaMin_C: -55; TaMax_C: 125
C37 = GRM21BR71H474KA88L: CAP, CERM, 0.47 µF, 50 V, +/- 10%, X7R, 0805; Manufacturer: MuRata; Polarized: N; CompType: Capacitor; Value: 0.47uF; U/M: EA; Cap_F: 0.00000047; Tolerance_%: 10; Value1: Unknown; VDC_V: 50; Value2: 50V; TaMin_C: -55; TaMax_C: 125; Cap_Case: 0805
C38 = C1608X7R1H473K: CAP, CERM, 0.047 µF, 50 V, +/- 10%, X7R, 0603; Manufacturer: TDK; Polarized: N; CompType: Capacitor; Value: 0.047uF; U/M: EA; Cap_F: 0.000000047; Tolerance_%: 10; ESR_ohm: 0.0234; Value1: 0.0234 ohm; VDC_V: 50; Value2: 50V; TaMin_C: -55; TaMax_C: 125
C39 C40 = VY2102M29Y5UG63V7: CAP CER 4700PF 440VAC Y5U RADIAL; Manufacturer: Vishay-Bccomponents; Polarized: N; CompType: Capacitor; U/M: EA; Tolerance_%: 20; Value1: Unknown; Value2: 300; TaMin_C: -40; TaMax_C: 125; Cap_Case: Radial Disc 7.5mm, ls=7.5; AEC Category: Q200
D6 = HLMP1523: LED SS HI EFF GREEN DIFF 3MM; Manufacturer: Everlight; Vf_V: 2.2; Value2: 2.2V; Io_A: 0.02; Tjmax_C: 100; Value1: W; U/M: EA
D7 = SMCJ100A: TVS DIODE 128VWM 207VC AXIAL; Manufacturer: Littelfuse; Power_W: 1500; Vr_V: 128; Value1: 1500W
D8 = RS3K-E3/9AT: Diode, Switching, 1000 V, 3 A, SMC; Manufacturer: STMicroelectronics; Vf_V: 1.7; Value: 1000V; Value1: 3A; Value2: 1.7V; Io_A: 3; Vr_V: 1000; TJmax_C: 150
D9 = BAV23S-7-F: Diode, Switching, 200 V, 0.4 A, SOT-23; Manufacturer: Diodes Inc.; U/M: EA; Vf_V: 1.25; Value: 200V; Value1: 0.4A; Value2: 1.25V; Io_A: 0.4; Vr_V: 200; TJmax_C: 150; RJC_CperW: 357
D11 = MMSZ5252B-7-F: Diode, Zener, 24V, 500mW, SOD-123; Manufacturer: Diodes Inc.; SymbolCreator: a0412235; U/M: EA; Power_W: 0.5; Vz_V: 24; Value1: 0.5W; RJA_CperW: 350
D12 = BZT52C4V7T-7: Diode, Zener, 4.7 V, 300 mW, SOD-523; Manufacturer: Diodes Inc.; U/M: EA; SymbolCreator: a0412235; Power_W: 0.3; Vz_V: 4.7; Value1: 0.3W; RJA_CperW: 417
HS2 = 593002B00000G: as HS1 on sheet TIDA-00701_PFC
HS3 = 593002B00000G: HEATSINK TO-220 19.05X13.21MM; Manufacturer: Assmann WSW Components; SymbolCreator: a0799628; Value: 21.0°C/W
J2 = 1715747: Terminal Block, 5.08mm, 4x1, TH; Manufacturer: Phoenix Contact; SymbolCreator: a0411947; U/M: EA
L4 = 744823210: Coupled inductor, 110uH min,  0.007 ohm; Manufacturer: Wurth Elektronik; Ind_H: 110e-6; DCR_ohm: 0.007
Q2 = IPP50R199CP: MOSFET N-CH 650V 15A TO220F; Manufacturer: Alpha & Omega Semiconductor Inc.; Alternate Manufacturer: None; U/M: EA; ChType: N; VdsMax_V: 650; Value1: 290 mohm; Rdson45_ohm: 0; Value2: 34 nC; QgTyp_nC: 34; Vgs_V: 20
Q3 = IRFB4410ZPBF: MOSFET N-CH 200V 26A TO-220FP; Manufacturer: International Rectifier; Alternate Manufacturer: None; U/M: EA; ChType: N; VdsMax_V: 200; Value1: 25 mOhm @ 17A, 10V; Value2: 100 nC; QgTyp_nC: 100nC at 10V; Vgs_V: 20; IdsMax_A: 97
Q4 = CSD18504Q5A: MOSFET, N-CH, 40 V, 15 A, SON 5x6mm; Manufacturer: Texas Instruments; Alternate Manufacturer: None; U/M: EA; ChType: N; Value: 40V; VdsMax_V: 40; Value1: 0.0098 ohm; Rdson45_ohm: 0.0098; Value2: 7.7 nC; QgTyp_nC: 7.7; Vgs_V: 20; IdsMax_A: 15
Q6 = CMST2222A TR, Central Semiconductor: Transistor, NPN, 40 V, 0.6 A, SOT-323; Manufacturer: ON Semiconductor; CompType: BJT; PNP: 0; NPN: 1; Vceo_V: 40; Vcesat1_V: 0.3; Value: 40 V; IcRated_A: 0.6; Value1: 0.6 A; TaMin_C: -65; TaMax_C: 150; U/M: EA
Q7 = MMBT2907A, Fairchild Semiconductor: Transistor, PNP, 40 V, 0.6 A, SOT-323; Manufacturer: ON Semiconductor; CompType: BJT; PNP: 1; NPN: 0; Vceo_V: 40; Vcesat1_V: 0.75; Value: 40 V; IcRated_A: 0.8; Value1: 0.6 A; HfeMax: 300; TaMin_C: -55; TaMax_C: 150; U/M: EA
R13 R47 R57 = CRCW0603100KFKEA: as R33 on sheet TIDA-00701_PFC
R26 = CSRN2010FKR750: RES, 0.75, 1%, 1 W, 2010; Manufacturer: Stackpole Electronics Inc; CompType: Resistor; Value: 0.75; Value_Code: R750; Tolerance_%: 1; Value2: 1W; TempCo: 250 ppm/C; EIA_Code: E96; U/M: EA; AEC Category: Q200
R27 = CSRN2010FKR250: RES, 0.25, 1%, 1 W, 2010; Manufacturer: Stackpole Electronics Inc; CompType: Resistor; Value: 0.25; Value_Code: R250; Tolerance_%: 1; Value2: 1W; TempCo: 250 ppm/C; U/M: EA; AEC Category: Q200
R28 = CRCW06035R10JNEA: RES, 5.1, 5%, 0.1 W, 0603; Manufacturer: Vishay-Dale; CompType: Resistor; Value: 5.1; Value_Code: 5R10; Tolerance_%: 5; Power_W: 0.1; Value2: 0.1W; VDC_V: 75; TempCo: 200 ppm/C; EIA_Code: E24; U/M: EA; AEC Category: Q200
R29 R55 = CRCW06031K21FKEA: RES, 1.21 k, 1%, 0.1 W, 0603; Manufacturer: Vishay-Dale; CompType: Resistor; Value: 1.21k; Res_ohm: 1210; Value_Code: 1k21; Tolerance_%: 1; Power_W: 0.1; Value2: 0.1W; VDC_V: 75; TempCo: 100 ppm/C; EIA_Code: E96; U/M: EA; AEC Category: Q200
R30 = CRCW080547R5FKEA: RES, 47.5, 1%, 0.125 W, 0805; Manufacturer: Vishay-Dale; CompType: Resistor; Value: 47.5; Value_Code: 47R5; Tolerance_%: 1; Power_W: 0.125; Value2: 0.125W; VDC_V: 150; TempCo: 100 ppm/C; EIA_Code: E96; U/M: EA
R31 = CRCW060371K5FKEA: RES, 71.5 k, 1%, 0.1 W, 0603; Manufacturer: Vishay-Dale; CompType: Resistor; Value: 71.5k; Res_ohm: 71500; Value_Code: 71k5; Tolerance_%: 1; Power_W: 0.1; Value2: 0.1W; VDC_V: 75; TempCo: 100 ppm/C; EIA_Code: E96; U/M: EA
R32 = CRCW060319K6FKEA: RES, 19.6 k, 1%, 0.1 W, 0603; Manufacturer: Vishay-Dale; CompType: Resistor; Value: 19.6k; Res_ohm: 19600; Value_Code: 19k6; Tolerance_%: 1; Power_W: 0.1; Value2: 0.1W; VDC_V: 75; TempCo: 100 ppm/C; EIA_Code: E96; U/M: EA
R34 = CRCW060320K5FKEA: RES, 20.5 k, 1%, 0.1 W, 0603; Manufacturer: Vishay-Dale; CompType: Resistor; Value: 20.5k; Res_ohm: 20500; Value_Code: 20k5; Tolerance_%: 1; Power_W: 0.1; Value2: 0.1W; VDC_V: 75; TempCo: 100 ppm/C; EIA_Code: E96; U/M: EA
R36 = CRCW06030000Z0EA: RES, 0, 5%, 0.1 W, 0603; Manufacturer: Vishay-Dale; CompType: Resistor; Value: 0; Value_Code: 0000; Tolerance_%: 5; Power_W: 0.1; Value2: 0.1W; VDC_V: 75; TempCo: 200 ppm/C; EIA_Code: E24; U/M: EA; AEC Category: Q200
R37 = CRCW0603402RFKEA: RES, 402, 1%, 0.1 W, 0603; Manufacturer: Vishay-Dale; CompType: Resistor; Value: 402; Value_Code: 402R; Tolerance_%: 1; Power_W: 0.1; Value2: 0.1W; VDC_V: 75; TempCo: 100 ppm/C; EIA_Code: E96; U/M: EA
R38 R42 = CRCW0603750KFKEA: RES, 750 k, 1%, 0.1 W, 0603; Manufacturer: Vishay-Dale; CompType: Resistor; Value: 750k; Res_ohm: 750000; Tolerance_%: 1; Power_W: 0.1; Value2: 0.1W; VDC_V: 75; TempCo: 100 ppm/C; EIA_Code: E96; U/M: EA
R39 R40 = CRCW060310K0FKEA: as R16 on sheet TIDA-00701_PFC
R41 = CRCW060347K5FKEA: RES, 47.5 k, 1%, 0.1 W, 0603; Manufacturer: Vishay-Dale; CompType: Resistor; Value: 47.5k; Res_ohm: 47500; Value_Code: 47k5; Tolerance_%: 1; Power_W: 0.1; Value2: 0.1W; VDC_V: 75; TempCo: 100 ppm/C; EIA_Code: E96; U/M: EA
R43 = CRCW060320K0FKEA: RES, 20.0 k, 1%, 0.1 W, 0603; Manufacturer: Vishay-Dale; CompType: Resistor; Value: 20.0k; Res_ohm: 20000; Value_Code: 20k0; Tolerance_%: 1; Power_W: 0.1; Value2: 0.1W; VDC_V: 75; TempCo: 100 ppm/C; EIA_Code: E96; U/M: EA
R44 = CRCW06031R50FKEA: RES, 1.50, 1%, 0.1 W, 0603; Manufacturer: Vishay-Dale; CompType: Resistor; Value: 1.50; Res_ohm: 1.5; Value_Code: 1R50; Tolerance_%: 1; Power_W: 0.1; Value2: 0.1W; VDC_V: 75; TempCo: 100 ppm/C; EIA_Code: E96; U/M: EA
R45 = CRCW1206100RFKEA: RES, 100, 1%, 0.25 W, 1206; Manufacturer: Vishay-Dale; CompType: Resistor; Value: 100; Value_Code: 100R; Tolerance_%: 1; Power_W: 0.25; Value2: 0.25W; VDC_V: 200; TempCo: 100 ppm/C; EIA_Code: E96; U/M: EA
R46 = CRCW060347R5FKEA: RES, 47.5, 1%, 0.1 W, 0603; Manufacturer: Vishay-Dale; CompType: Resistor; Value: 47.5; Value_Code: 47R5; Tolerance_%: 1; Power_W: 0.1; Value2: 0.1W; VDC_V: 75; TempCo: 100 ppm/C; EIA_Code: E96; U/M: EA
R48 = CRCW060344K2FKEA: RES, 44.2 k, 1%, 0.1 W, 0603; Manufacturer: Vishay-Dale; CompType: Resistor; Value: 44.2k; Res_ohm: 44200; Value_Code: 44k2; Tolerance_%: 1; Power_W: 0.1; Value2: 0.1W; VDC_V: 75; TempCo: 100 ppm/C; EIA_Code: E96; U/M: EA
R49 = CRCW06031K00FKEA: RES, 1.00 k, 1%, 0.1 W, 0603; Manufacturer: Vishay-Dale; CompType: Resistor; Value: 1.00k; Res_ohm: 1000; Value_Code: 1k00; Tolerance_%: 1; Power_W: 0.1; Value2: 0.1W; VDC_V: 75; TempCo: 100 ppm/C; EIA_Code: E96; U/M: EA
R50 = CRCW06031K50FKEA: RES, 1.50 k, 1%, 0.1 W, 0603; Manufacturer: Vishay-Dale; CompType: Resistor; Value: 1.50k; Res_ohm: 1500; Value_Code: 1k50; Tolerance_%: 1; Power_W: 0.1; Value2: 0.1W; VDC_V: 75; TempCo: 100 ppm/C; EIA_Code: E96; U/M: EA
R51 = CRCW06034K99FKEA: RES, 4.99 k, 1%, 0.1 W, 0603; Manufacturer: Vishay-Dale; CompType: Resistor; Value: 4.99k; Res_ohm: 4990; Value_Code: 4k99; Tolerance_%: 1; Power_W: 0.1; Value2: 0.1W; VDC_V: 75; TempCo: 100 ppm/C; EIA_Code: E96; U/M: EA
R52 = CRCW060310K0FKEA: RES, 10.0 k, 1%, 0.1 W, 0603; Manufacturer: Vishay-Dale; CompType: Resistor; Value: 10.0k; U/M: EA; Res_ohm: 10000; Value_Code: 10k0; Tolerance_%: 1; Power_W: 0.1; Value2: 0.1W; VDC_V: 75; TempCo: 100 ppm/C; EIA_Code: E96
R53 = CRCW1206100KFKEA: RES, 100 k, 1%, 0.25 W, 1206; Manufacturer: Vishay-Dale; CompType: Resistor; Value: 100k; Res_ohm: 100000; Tolerance_%: 1; Power_W: 0.25; Value2: 0.25W; VDC_V: 200; TempCo: 100 ppm/C; EIA_Code: E96; U/M: EA
R54 = RC0603FR-07470KL: RES, 470 k, 1%, 0.1 W, 0603; Manufacturer: Yageo America; CompType: Resistor; Value: 470k; Res_ohm: 470000; Tolerance_%: 1; Power_W: 0.1; Value2: 0.1W; VDC_V: 150; TempCo: 200 ppm/C; U/M: EA
R56 = CRCW0603332KFKEA: RES, 332 k, 1%, 0.1 W, 0603; Manufacturer: Vishay-Dale; CompType: Resistor; Value: 332k; Res_ohm: 332000; Tolerance_%: 1; Power_W: 0.1; Value2: 0.1W; VDC_V: 75; TempCo: 100 ppm/C; EIA_Code: E96; U/M: EA
R58 = 3266W-1-203LF: TRIMMER 100K OHM 0.5W TH; Manufacturer: TT Electronics/BI; Sim Note: Enter the Resistance value and the set point into parameter fields.
T1 = 750343004: TRANSFORMER, 160.0uH, 10%, TH-10PIN; Manufacturer: WURTH ELEKTRONIK; SymbolCreator: x0199378
TP7 TP9 = 5001: as TP4 on sheet TIDA-00701_PFC
TP8 = 5000: as TP1 on sheet TIDA-00701_PFC
U2 = UCC28740DR: Constant-Voltage, Constant-Current Flyback Controller Using Opto-Coupler Feedback, D0007A; Manufacturer: Texas Instruments; SymbolCreator: a0412235; CompType: IC; U/M: EA
U3 = UCC24630DBV: SYNCRONOUS RECTIFIER CONTROLLER WITH LOW POWER STANDBY, DBV0006A; Manufacturer: Texas Instruments; SymbolCreator: a0411947; CompType: IC; U/M: EA
U4 = TL431BQDBZ: as U8 on sheet TIDA-00701_PFC
U5 = LM5050-2: HIGH SIDE OR-ING FET CONTROLLER; Manufacturer: Used in BOM report; SymbolVersion: use current date i.e. 2008-05-20; SymbolCreator: Use LDAP id; CompType: Used in some BOM reports.  Useful for finding later.; U/M: EA, IN, or GM
U6 = LTV-817: Optocoupler, 5 kV, 50-600% CTR, TH-4; Manufacturer: Lite-On; U/M: EA; CTR_Min: 50% @ 5mA; CTR_Max: 600% @ 5mA; Voltage_Isolation_Vrms: 5000; tr_typ: 4us; tf_typ: 3us

## Sheet Hardware_ANSI-B.SchDoc
size 431 x 279 mm; Date: Not shown in title block; ApprovedBy: Not shown in title block; CheckedBy: Not shown in title block; Author: Not shown in title block; CompanyName: Not shown in title block; DrawnBy: Latif Ameer; Engineer: Not shown in title block; Organization: Not shown in title block; Address1: Not shown in title block; Address2: Not shown in title block; Address3: Not shown in title block; Address4: Not shown in title block; DocumentNumber: 1; Revision: Use project parameter SCH_Rev; SheetNumber: 3; SheetTotal: 3; PageSetup: Record=PageOptions¦CenterHorizontal=True¦CenterVertical=True¦PrintScale=1.00¦XCorrection=1.00¦YCorrection=1.00¦PrintKind=0¦BorderSize=5000000¦LeftOffset=0¦BottomOffset=0¦Orientation=2¦PaperLength=1000¦PaperWidth=1000¦Scale=100¦PaperSource=15¦PrintQuality=600¦MediaType=1¦DitherType=10¦PaperKind=Letter¦PrintScaleMode=1
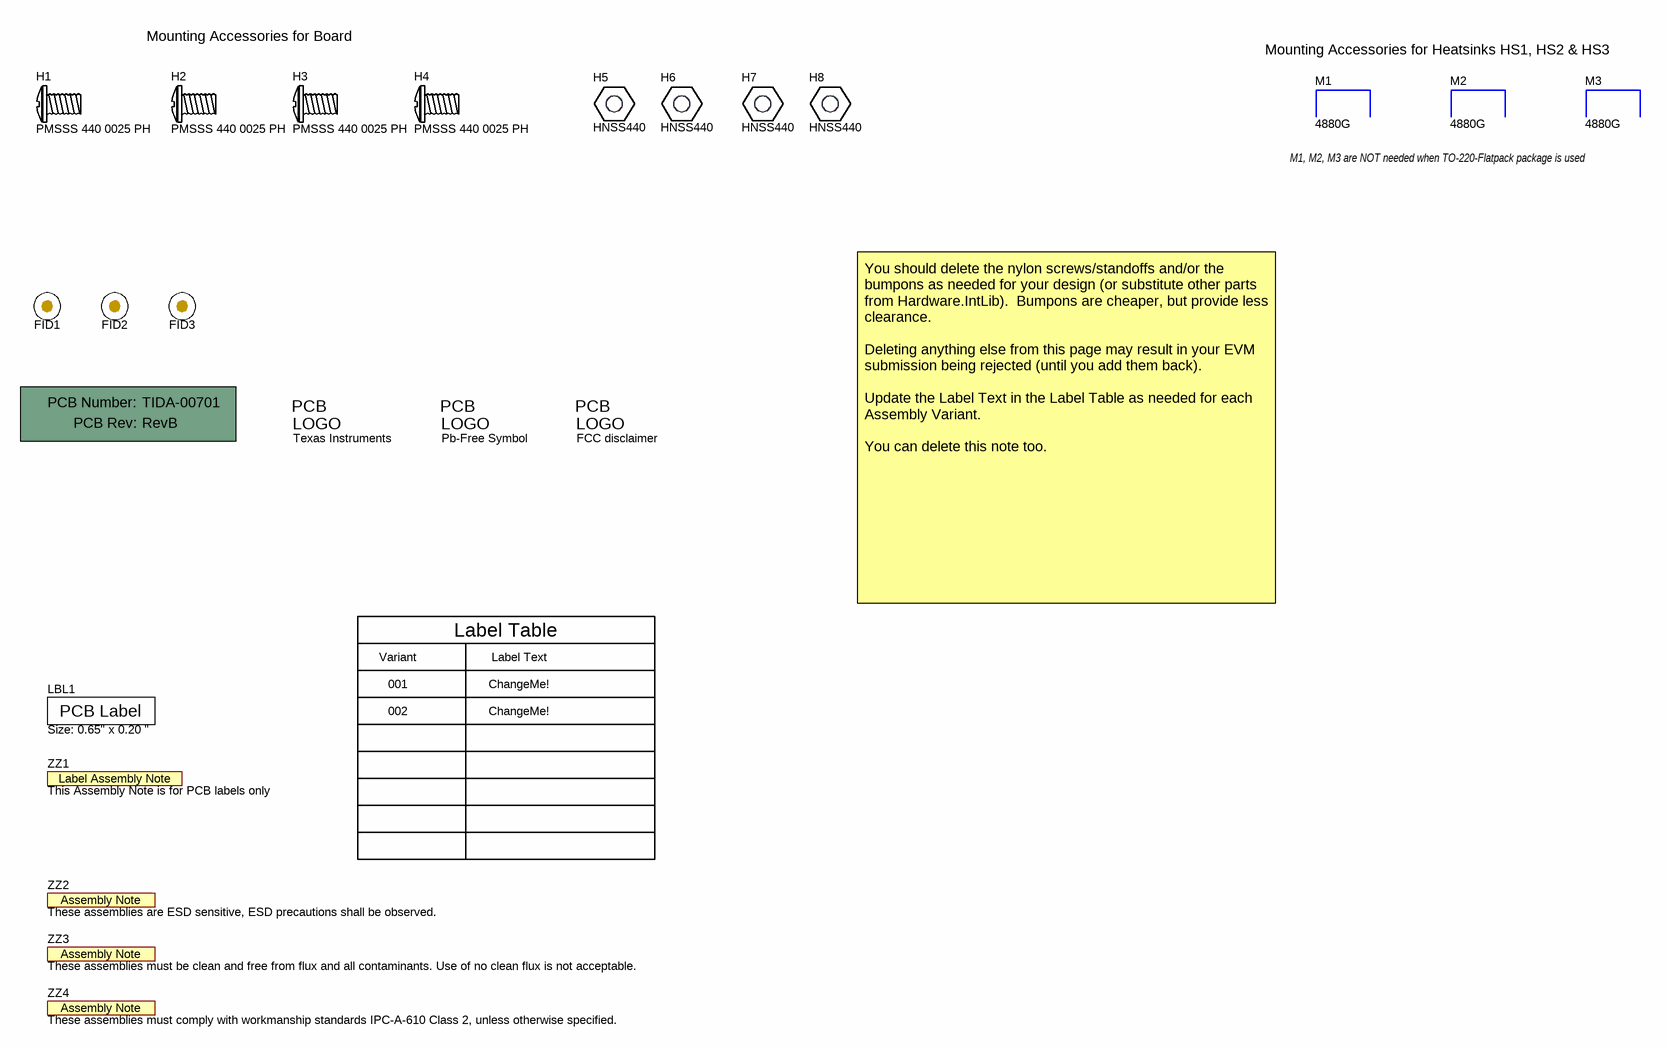
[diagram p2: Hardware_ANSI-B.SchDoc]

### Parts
!PCB1  Printed Circuit Board  (value not drawn)  (mechanical)
FID1  Fiducial  [Fiducial10-20]  (value not drawn)
FID2  Fiducial  [Fiducial10-20]  (value not drawn)
FID3  Fiducial  [Fiducial10-20]  (value not drawn)
H1  PMSSS 440 0025 PH  [B_F_PMSSS4400025PH]
H2  PMSSS 440 0025 PH  [B_F_PMSSS4400025PH]
H3  PMSSS 440 0025 PH  [B_F_PMSSS4400025PH]
H4  PMSSS 440 0025 PH  [B_F_PMSSS4400025PH]
H5  HNSS440
H6  HNSS440
H7  HNSS440
H8  HNSS440
LBL1  Size: 0.65" x 0.20 "  [Label_650x200]
Logo1  Texas Instruments  [TI_STACKED_OVERLAY_SMALL]  (no BOM)
Logo2  Pb-Free Symbol  [Pb-Free_Overlay_Small]  (no BOM)
Logo3  FCC disclaimer  [FCC_disclaimer]  (no BOM)
M1  4880G
M2  4880G
M3  4880G
ZZ1  This Assembly Note is for PCB labels only  [AssemblyNoteLabel]  (no BOM)
ZZ2  These assemblies are ESD sensitive, ESD precautions shall be observed.  [AssemblyNote]  (no BOM)
ZZ3  These assemblies must be clean and free from flux and all contaminants. Use of no clean flux is not acceptable.  [AssemblyNote]  (no BOM)
ZZ4  These assemblies must comply with workmanship standards IPC-A-610 Class 2, unless otherwise specified.  [AssemblyNote]  (no BOM)

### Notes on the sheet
- Mounting Accessories for Board
- Mounting Accessories for Heatsinks HS1, HS2 & HS3
- M1, M2, M3 are NOT needed when TO-220-Flatpack package is used
- Variant
- Label Table
- Label Text
- You should delete the nylon screws/standoffs and/or the bumpons as needed for your design (or substitute other parts from Hardware.IntLib).  Bumpons are cheaper, but provide less clearance.
  Deleting anything else from this page may result in your EVM submission being rejected (until you add them back).
  Update the Label Text in the Label Table as needed for each Assembly Variant.
  You can delete this note too.
- 001
- 002
- ChangeMe!

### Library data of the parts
!PCB1 = PCB: Manufacturer: Any; PartNumber: TIDA-00701; SymbolCreator: a0412235
FID1-FID3 = Fiducial: Fiducial mark.  There is nothing to buy or mount.; SymbolCreator: codlsc
H1-H4 = PMSSS 440 0025 PH: MACHINE SCREW PAN PHILLIPS 4-40; Manufacturer: B&F Fastener Supply; SymbolCreator: a0412235; CompType: Standoff
H5-H8 = SMTSO-440-2ET: HEX NUT 1/4" STN STEEL 4-40; Manufacturer: B&F Fastener Supply; SymbolCreator: a0412235; CompType: Hardware
LBL1 = THT-14-423-10: Thermal Transfer Printable Labels, 0.650" W x 0.200" H - 10,000 per roll; Manufacturer: Brady; SymbolCreator: a0412235; CompType: Label
Logo1 = TI_Logo: Texas Instrument Corporate Signature; SymbolCreator: a0412235
Logo2 = Pb-Free: SymbolCreator: a0412235
Logo3 = FCC_disclaimer: SymbolCreator: codlsc
M1-M3 = PCC-SMP-CLIP: MOUNTING KIT TO-220; Manufacturer: Aavid Thermalloy; SymbolCreator: Altium; CompType: Hardware
ZZ1 = AssemblyNoteLabel: SymbolCreator: a0412235
ZZ2-ZZ4 = AssemblyNote: SymbolCreator: codlsc

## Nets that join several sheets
GND: TIDA-00701_PFC (28 pins), TIDA-00701_Flyback (17 pins)
GNDE: TIDA-00701_PFC (5 pins), TIDA-00701_Flyback (C39.2 C40.2)
NetC2_1: TIDA-00701_PFC (C2.1 D1.1 D2.1 R6.1), TIDA-00701_Flyback (6 pins)
NetC36_1: TIDA-00701_PFC (Q8.3), TIDA-00701_Flyback (C36.1 R29.1 U2.5)
VCC: TIDA-00701_PFC (C9.1 R35.1 TP3.1 U1.8), TIDA-00701_Flyback (C19.1 D9.3)

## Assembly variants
001: not fitted C5 C6 C28 Q6 Q7 R2 R45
